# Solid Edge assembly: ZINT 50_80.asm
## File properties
Title: Zylinder
Author: bmolnar
Template: iso metric assembly.asm
Last saved by: bmolnar
Revision: 20
Application: Solid Edge
Username: bmolnar
Dokumentum tartalom típus: 1
Document Number: ZINT 50/80
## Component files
hrungsstange.par
Profilrohr.par
Platte.par
Kolbenstange.par
Kit_2.par
Kit_1.par
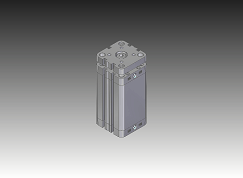
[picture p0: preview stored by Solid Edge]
